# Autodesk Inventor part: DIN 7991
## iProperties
Author: Cor de Vlaming
Shininess: 64.0
Angle Display Precision: 2
Document Length Units: 11269
Document Angle Units: 11283
Document Time Units: 11279
Document Mass Units: 11290
Document Length Units Precision: 3
Document Angle Units Precision: 2
Compacted: True
PropertySet Name: _Private Model Information
Created: 2002-10
Part Number: DIN 7991
Document SubType Name: Modeling
Designer: Cor de Vlaming
Control State: 0
Master: False
Checked Out: False
PropertySet Name: Design Tracking Control
Density: 0.0
Volumn: 0.0
Area: 0.0
PropertySet Name: Model Information
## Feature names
1. Revolution1
2. Chamfer1
3. Hole1
4. Extrusion1
5. Fillet1
